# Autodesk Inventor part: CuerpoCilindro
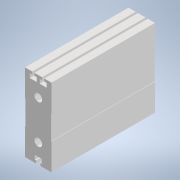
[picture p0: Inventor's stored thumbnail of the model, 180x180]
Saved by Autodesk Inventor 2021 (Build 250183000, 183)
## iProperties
Created: 2021-02
Part Number: CuerpoCilindro
Material: Genérico
Document SubType Name: Modeling
Designer: ATOUZA
Density: 1 g/cm^3
Appearance: Valor por defecto
Author: ATOUZA
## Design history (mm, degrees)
sketch "Boceto1"
  geometry: L1 (-17.125, -50.2)-(17.125, 50.2); L2 (17.125, -50.2)-(-17.125, 50.2); L3 (-2.8, -50.2)-(-2.8, -46.8); L4 (-2.8, -46.8)-(-4.5, -46.8); L5 (-4.5, -46.8)-(-4.5, -41.4); L6 (-4.5, -41.4)-(0, -41.4); L7 (0, -50.2)-(0, 50.2); L8 (2.8, -50.2)-(2.8, -46.8); L9 (2.8, -46.8)-(4.5, -46.8); L10 (4.5, -46.8)-(4.5, -41.4); L11 (4.5, -41.4)-(0, -41.4); L12 (-17.125, -50.2)-(-2.8, -50.2); L13 (2.8, -50.2)-(17.125, -50.2); L14 (-7.8, 50.2)-(-7.8, 46.8); L15 (-7.8, 46.8)-(-10.9, 46.8); L16 (-10.9, 46.8)-(-10.9, 41.4); L17 (-10.9, 41.4)-(-1.9, 41.4); L18 (-1.9, 41.4)-(-1.9, 46.8); L19 (-1.9, 46.8)-(-5, 46.8); L20 (-5, 46.8)-(-5, 50.2); L21 (10.9, 46.8)-(10.9, 41.4); L22 (10.9, 41.4)-(1.9, 41.4); L23 (1.9, 41.4)-(1.9, 46.8); L24 (1.9, 46.8)-(5, 46.8); L25 (5, 46.8)-(5, 50.2); L26 (7.8, 50.2)-(7.8, 46.8); L27 (7.8, 46.8)-(10.9, 46.8); L28 (-7.8, 50.2)-(-17.125, 50.2); L29 (17.125, 50.2)-(7.8, 50.2); L30 (5, 50.2)-(-5, 50.2); L31 (-17.125, 0)-(17.125, 0); L32 (-17.125, -15.5)-(-16.625, -15.5); L33 (-16.625, -15.5)-(-16.625, 15.5); L34 (-16.625, 15.5)-(-17.125, 15.5); L35 (-17.125, 50.2)-(-17.125, 15.5); L36 (-17.125, -15.5)-(-17.125, -50.2); L37 (16.625, -15.5)-(16.625, 15.5); L38 (17.125, -15.5)-(16.625, -15.5); L39 (16.625, 15.5)-(17.125, 15.5); L40 (17.125, -50.2)-(17.125, -15.5); L41 (17.125, 15.5)-(17.125, 50.2); C1 r 5 at (0, -25); C2 r 5 at (0, 25); 1 further point
  constraints: 82 end point, 17 perpendicular, 17 symmetric about line, 10 parallel, 6 point on line, 3 horizontal, 3 midpoint, 3 vertical, 2 centre point, 1 other
  dimensions: "d0" = 34.25 distance of L2.end L1.end; "d1" = 100.4 distance of L1.end L2.start; "d2" = 2.8 distance between parallel lines of L3 L7; "d3" = 4.5 distance between parallel lines of L5 L7; "d5" = 5.4 distance between parallel lines of L6 L4; "d6" = 3.4 distance of L3.start L3.end; "d8" = 5.4 distance between parallel lines of L17 L15; "d9" = 9 distance of L16.end L17.end; "d10" = 2.8 distance between parallel lines of L14 L20; "d11" = 3.1 distance between parallel lines of L20 L18; "d12" = 5 distance between parallel lines of L7 L20; "d13" = 10 diameter of C1; "d14" = 25 distance of point (0, 0) C1.centre; "d15" = 31 distance between parallel lines of L32 L34; "d16" = 15.5 distance between parallel lines of L31 L34
extrude "Extrusión1" new body sketch "Boceto1" distance "d18" = 133.75; taper "d19" = 0 deg
node "Sólido1"
other parameters: "d4" = 3.4, "d7" = 3.4, "d17" = 0.5
